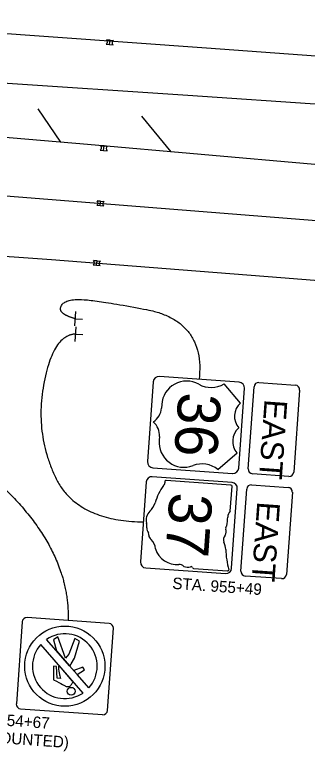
# Model space of a CAD drawing. Extents: x 1847379 to 1850904, y 217032 to 220169.
# Drawn here: x 1849667.4 to 1849731.4, y 218655.8 to 218816.8 of the extents above; entities that cross this region are included whole.
import ezdxf

# ---------------------------------------------------------------- set-up
doc = ezdxf.new("R2010")
doc.units = 0
for name, color, linetype in [('PM_P_Cells', 7, 'Continuous'), ('PM_P_CL_Double_Solid', 7, 'Continuous'), ('PM_P_Edge_Line', 7, 'Continuous'), ('PM_P_Lane_Line', 7, 'Continuous'), ('PM_P_Transverse_Line', 7, 'Continuous'), ('SN_X_Public', 7, 'Continuous'), ('SN_X_Text', 7, 'Continuous')]:
    doc.layers.add(name, color=color, linetype=linetype)

msp = doc.modelspace()

# ---------------------------------------------------------------- linework, layer by layer
at = {"layer": 'PM_P_Cells'}
for p, q in [((1849687.36, 218810.41), (1849688.13, 218810.34)), ((1849687.36, 218810.41), (1849688.13, 218810.34)), ((1849688.22, 218811.31), (1849687.45, 218811.38)), ((1849687.45, 218811.38), (1849688.22, 218811.31)), ((1849688.13, 218810.34), (1849688.22, 218811.31)), ((1849688.13, 218810.34), (1849688.9, 218810.27)), ((1849688.22, 218811.31), (1849688.98, 218811.24)), ((1849686.91, 218788.14), (1849686.14, 218788.21)), ((1849686.14, 218788.21), (1849686.91, 218788.14)), ((1849686.82, 218787.17), (1849686.91, 218788.14)), ((1849686.91, 218788.14), (1849687.68, 218788.07)), ((1849686.05, 218787.24), (1849686.82, 218787.17)), ((1849686.05, 218787.24), (1849686.82, 218787.17)), ((1849686.82, 218787.17), (1849687.59, 218787.1)), ((1849685.31, 218775.18), (1849686.08, 218775.11)), ((1849685.31, 218775.18), (1849686.08, 218775.11)), ((1849686.17, 218776.08), (1849685.4, 218776.15)), ((1849685.4, 218776.15), (1849686.17, 218776.08)), ((1849686.08, 218775.11), (1849686.17, 218776.08)), ((1849686.08, 218775.11), (1849686.85, 218775.04)), ((1849686.17, 218776.08), (1849686.94, 218776.01)), ((1849684.51, 218762.14), (1849685.28, 218762.07)), ((1849684.51, 218762.14), (1849685.28, 218762.07)), ((1849685.37, 218763.05), (1849684.6, 218763.12)), ((1849684.6, 218763.12), (1849685.37, 218763.05)), ((1849685.28, 218762.07), (1849685.37, 218763.05)), ((1849685.28, 218762.07), (1849686.05, 218762.01)), ((1849685.37, 218763.05), (1849686.14, 218762.98))]:
    msp.add_line(p, q, dxfattribs=at)
for centre, start, end in [((1849687.1, 218810.92), 296.8063, 52.8586), ((1849687.1, 218810.92), 296.8063, 52.8586), ((1849689.24, 218810.73), 116.8063, 232.8586), ((1849685.79, 218787.75), 296.8063, 52.8586), ((1849685.79, 218787.75), 296.8063, 52.8586), ((1849687.94, 218787.56), 116.8063, 232.8586), ((1849685.05, 218775.69), 296.8063, 52.8586), ((1849685.05, 218775.69), 296.8063, 52.8586), ((1849687.2, 218775.5), 116.8063, 232.8586), ((1849684.25, 218762.66), 296.8063, 52.8586), ((1849684.25, 218762.66), 296.8063, 52.8586), ((1849686.4, 218762.46), 116.8063, 232.8586)]:
    msp.add_arc(centre, 0.576, start, end, dxfattribs=at)
at = {"layer": 'PM_P_CL_Double_Solid'}
for p, q in [((1849693.11, 218799.32), (1849693.11, 218799.32)), ((1849683.32, 218788.47), (1849634.02, 218792.58)), ((1849733.07, 218784.06), (1849683.32, 218788.47))]:
    msp.add_line(p, q, dxfattribs=at)
at = {"layer": 'PM_P_Edge_Line'}
for p, q in [((1849655.22, 218802.6), (1849705.27, 218799.28)), ((1849705.27, 218799.28), (1849757.46, 218795.73))]:
    msp.add_line(p, q, dxfattribs=at)
msp.add_lwpolyline([(1849624.07, 218766.93), (1849675.44, 218763.35), (1849725.59, 218759.36), (1849777.06, 218755.28), (1849832.17, 218750.77)], dxfattribs=at)
at = {"layer": 'PM_P_Lane_Line'}
msp.add_line((1849606.07, 218781.96), (1849881.96, 218760.04), dxfattribs=at)
msp.add_lwpolyline([(1849608.14, 218816.84), (1849659.46, 218813.21), (1849709.31, 218809.62), (1849760.21, 218805.9), (1849807.22, 218802.44), (1849857.63, 218799.12), (1849906.82, 218795.7), (1849957.46, 218791.82), (1850014.55, 218787.19), (1850067.13, 218782.71), (1850118.03, 218778.2), (1850167.47, 218773.95), (1850186.14, 218772.34)], dxfattribs=at)
at = {"layer": 'PM_P_Transverse_Line'}
for p, q in [((1849672.4, 218796.24), (1849677.4, 218788.96)), ((1849695.12, 218794.63), (1849701.53, 218786.86))]:
    msp.add_line(p, q, dxfattribs=at)
at = {"layer": 'SN_X_Public'}
for p, q in [((1849680.52, 218748.78), (1849680.76, 218751.97)), ((1849680.64, 218750.37), (1849682.23, 218750.25)), ((1849680.57, 218745.42), (1849680.81, 218748.61)), ((1849680.69, 218747.02), (1849682.29, 218746.89)), ((1849716.78, 218731.93), (1849713.17, 218736.11)), ((1849720.81, 218736.42), (1849728.79, 218735.85)), ((1849718.46, 218717.54), (1849719.74, 218735.49)), ((1849729.72, 218734.78), (1849728.44, 218716.83)), ((1849699.53, 218731.6), (1849699.47, 218730.82)), ((1849699.03, 218724.58), (1849698.97, 218723.81)), ((1849711.83, 218717.41), (1849716.01, 218721.02)), ((1849727.37, 218715.9), (1849719.39, 218716.47)), ((1849714.69, 218713.98), (1849700.49, 218715)), ((1849714.53, 218708.3), (1849714.92, 218713.78)), ((1849719.21, 218714.05), (1849727.19, 218713.48)), ((1849716.87, 218695.17), (1849718.15, 218713.12)), ((1849728.12, 218712.41), (1849726.84, 218694.46)), ((1849706.52, 218695.77), (1849713.95, 218695.24)), ((1849706.52, 218695.77), (1849706.52, 218695.77)), ((1849725.77, 218693.53), (1849717.79, 218694.1)), ((1849676.81, 218680.78), (1849675.88, 218680.17)), ((1849676.81, 218680.78), (1849675.88, 218680.17)), ((1849675.88, 218680.17), (1849676.51, 218677.77)), ((1849675.88, 218680.17), (1849676.51, 218677.77)), ((1849678.45, 218676.14), (1849676.81, 218680.78)), ((1849678.45, 218676.14), (1849676.81, 218680.78)), ((1849680.53, 218680.43), (1849679.23, 218676.99)), ((1849680.53, 218680.43), (1849679.23, 218676.99)), ((1849680.42, 218676.14), (1849681.52, 218679.85)), ((1849680.42, 218676.14), (1849681.52, 218679.85)), ((1849681.52, 218679.85), (1849680.53, 218680.43)), ((1849681.52, 218679.85), (1849680.53, 218680.43)), ((1849682.31, 218668.52), (1849673.09, 218679.16)), ((1849676.51, 218677.77), (1849679.37, 218674.47)), ((1849679.23, 218676.99), (1849678.45, 218676.14)), ((1849679.23, 218676.99), (1849678.45, 218676.14)), ((1849679.42, 218674.41), (1849679.73, 218674.9)), ((1849679.42, 218674.41), (1849679.73, 218674.9)), ((1849679.73, 218674.9), (1849680.42, 218676.14)), ((1849679.73, 218674.9), (1849680.42, 218676.14)), ((1849676.47, 218674.33), (1849675.83, 218674.43)), ((1849675.83, 218674.43), (1849675.85, 218671.43)), ((1849676.47, 218674.33), (1849675.83, 218674.43)), ((1849675.83, 218674.43), (1849675.85, 218671.43)), ((1849676.65, 218671.78), (1849676.47, 218674.33)), ((1849676.65, 218671.78), (1849676.47, 218674.33)), ((1849680.04, 218671.13), (1849677.06, 218674.57)), ((1849679.37, 218674.47), (1849679.42, 218674.41)), ((1849682.3, 218674.2), (1849680.28, 218673.43)), ((1849682.3, 218674.2), (1849680.28, 218673.43)), ((1849680.28, 218673.43), (1849680.43, 218673.25)), ((1849681.04, 218672.55), (1849682.66, 218673.59)), ((1849681.04, 218672.55), (1849682.66, 218673.59)), ((1849682.66, 218673.59), (1849682.3, 218674.2)), ((1849682.66, 218673.59), (1849682.3, 218674.2)), ((1849677.38, 218671.7), (1849676.65, 218671.78)), ((1849677.38, 218671.7), (1849676.65, 218671.78)), ((1849675.85, 218671.43), (1849675.87, 218671.43)), ((1849675.85, 218671.43), (1849675.87, 218671.43)), ((1849680.14, 218671.02), (1849680.04, 218671.13))]:
    msp.add_line(p, q, dxfattribs=at)
for points in [[(1849716.48, 218736.5), (1849699.03, 218737.74)], [(1849697.69, 218736.58), (1849696.45, 218719.13)], [(1849716.4, 218717.71), (1849717.64, 218735.16)], [(1849697.6, 218717.79), (1849715.06, 218716.55)], [(1849714.92, 218714.58), (1849697.46, 218715.82)], [(1849696.13, 218714.67), (1849694.88, 218697.21)], [(1849714.83, 218695.79), (1849716.08, 218713.24)], [(1849696.04, 218695.87), (1849713.5, 218694.63)], [(1849688.02, 218683.74), (1849670.07, 218685.02)], [(1849669, 218684.09), (1849667.72, 218666.14)], [(1849687.67, 218664.71), (1849688.95, 218682.67)], [(1849680.43, 218673.25), (1849679.37, 218674.47), (1849675.93, 218678.43), (1849674.35, 218680.26)], [(1849683.58, 218669.62), (1849681.07, 218672.51), (1849680.42, 218673.25), (1849680.43, 218673.25)], [(1849680.43, 218673.25), (1849681.04, 218672.55), (1849681.04, 218672.55)], [(1849680.04, 218671.13), (1849680.04, 218671.13)], [(1849668.64, 218665.07), (1849686.6, 218663.79)]]:
    msp.add_lwpolyline(points, dxfattribs=at)
for centre, radius in [((1849678.33, 218674.39), 8.77), ((1849679.72, 218668.9), 0.864)]:
    msp.add_circle(centre, radius, dxfattribs=at)
for centre, radius, start, end in [((1849698.94, 218736.5), 1.25, 85.9213, 175.9213), ((1849704.99, 218731.27), 5.47, 60.7533, 176.5596), ((1849710.36, 218740.8), 5.47, 240.4685, 300.9223), ((1849716.39, 218735.25), 1.25, 355.9213, 85.9213), ((1849720.74, 218735.42), 1, 85.9213, 175.9213), ((1849728.72, 218734.85), 1, 355.9213, 85.9213), ((1849719.37, 218729.01), 3.91, 131.4943, 220.3483), ((1849695.58, 218731.1), 3.91, 302.7912, 355.9213), ((1849695.13, 218724.86), 3.91, 355.9213, 49.0514), ((1849718.98, 218723.55), 3.91, 131.4943, 220.3483), ((1849704.42, 218723.36), 5.47, 175.2831, 291.0894), ((1849697.69, 218719.04), 1.25, 175.9213, 265.9213), ((1849708.38, 218713.16), 5.47, 50.9204, 111.3742), ((1849715.15, 218717.8), 1.25, 265.9213, 355.9213), ((1849719.46, 218717.47), 1, 175.9213, 265.9213), ((1849727.44, 218716.9), 1, 265.9213, 355.9213), ((1849697.38, 218714.58), 1.25, 85.9213, 175.9213), ((1849711.84, 218705.96), 14.36, 146.3343, 163.1198), ((1849699.63, 218714.46), 0.603, 295.6697, 359.1931), ((1849701.89, 218714.64), 1.67, 173.2603, 186.5252), ((1849700.44, 218714.78), 0.219, 77.8797, 164.228), ((1849714.7, 218713.77), 0.217, 4.0514, 94.0514), ((1849714.83, 218713.33), 1.25, 355.9213, 85.9213), ((1849719.14, 218713.05), 1, 85.9213, 175.9213), ((1849727.12, 218712.48), 1, 355.9213, 85.9213), ((1849693.83, 218711.54), 4.49, 313.1055, 341.7573), ((1849698.98, 218706.3), 2.85, 136.6217, 192.2132), ((1849716.08, 218706.88), 2.11, 137.5409, 177.0332), ((1849693.95, 218705), 2.34, 351.6165, 17.1313), ((1849706.41, 218706.87), 7.56, 346.408, 0.9096), ((1849697.78, 218704.52), 1.52, 174.6984, 221.4706), ((1849712.42, 218703.83), 1.26, 320.388, 25.0625), ((1849714.12, 218704.6), 0.608, 125.7134, 203.0237), ((1849696.31, 218703.25), 0.428, 331.6731, 38.5698), ((1849698.27, 218703.29), 1.61, 188.7945, 229.1985), ((1849714.55, 218702.04), 1.52, 139.7776, 200.7495), ((1849695.42, 218700.04), 2.72, 0.3245, 48.4981), ((1849709.56, 218699.7), 4, 3.2675, 26.6902), ((1849702.87, 218701.61), 4.97, 198.2302, 274.9072), ((1849733.42, 218700.55), 19.88, 181.7658, 194.8278), ((1849696.13, 218697.12), 1.25, 175.9213, 265.9213), ((1849703.36, 218695.24), 1.41, 42.7278, 92.8509), ((1849705.19, 218697.97), 1.94, 245.9543, 289.5709), ((1849705.98, 218695.85), 0.323, 13.8653, 116.2583), ((1849706.51, 218695.99), 0.223, 195.5252, 273.6555), ((1849713.59, 218695.88), 1.25, 265.9213, 355.9213), ((1849713.99, 218695.44), 0.209, 257.7834, 3.6593), ((1849717.86, 218695.1), 1, 175.9213, 265.9213), ((1849725.84, 218694.53), 1, 265.9213, 355.9213), ((1849669.99, 218684.02), 1, 85.9213, 175.9213), ((1849687.95, 218682.74), 1, 355.9213, 85.9213), ((1849678.33, 218674.39), 7.09, 317.7693, 124.1693), ((1849678.33, 218674.39), 7.09, 317.7693, 124.1693), ((1849678.33, 218674.39), 7.09, 137.7404, 304.0927), ((1849668.71, 218666.06), 1, 175.9213, 265.9213), ((1849686.67, 218664.78), 1, 265.9213, 355.9213)]:
    msp.add_arc(centre, radius, start, end, dxfattribs=at)
for points in [[(1849677.06, 218674.57), (1849677.02, 218674.51), (1849676.94, 218674.31), (1849676.94, 218673.85), (1849677, 218673.43), (1849677.14, 218672.69), (1849677.26, 218672.18), (1849677.38, 218671.7)], [(1849677.06, 218674.57), (1849677.02, 218674.51), (1849676.94, 218674.31), (1849676.94, 218673.85), (1849677, 218673.43), (1849677.14, 218672.69), (1849677.26, 218672.18), (1849677.38, 218671.7)], [(1849675.87, 218671.43), (1849676.72, 218670.98), (1849678.06, 218670.25), (1849678.55, 218669.98), (1849678.72, 218669.94), (1849678.88, 218669.92), (1849679.28, 218669.9), (1849679.82, 218670.33), (1849680.01, 218670.76), (1849680.14, 218671.02)], [(1849675.87, 218671.43), (1849676.72, 218670.98), (1849678.06, 218670.25), (1849678.55, 218669.98), (1849678.72, 218669.94), (1849678.88, 218669.92), (1849679.28, 218669.9), (1849679.82, 218670.33), (1849680.01, 218670.76), (1849680.14, 218671.02)]]:
    msp.add_open_spline(points, degree=3, dxfattribs=at)
at = {"layer": 'SN_X_Text'}
for points in [[(1849680.64, 218750.37), (1849677.04, 218751.33), (1849677.78, 218754.34), (1849683.48, 218754.8), (1849708.98, 218749.93), (1849707.75, 218737.12)], [(1849680.69, 218747.02), (1849675.76, 218746.88), (1849671.7, 218725.5), (1849680.71, 218706.16), (1849695.51, 218705.94)], [(1849596.59, 218740), (1849622.52, 218734.68), (1849656.27, 218723.03), (1849679.46, 218697.82), (1849679.04, 218684.38)]]:
    msp.add_open_spline(points, degree=2, dxfattribs=at)

# ---------------------------------------------------------------- texts
at = {"layer": 'SN_X_Public'}
for s, height, p in [('36', 9.375, (1849703.25, 218734.42)), ('EAST', 5, (1849722.06, 218732.84)), ('37', 9.375, (1849701.32, 218712.53)), ('EAST', 5, (1849720.46, 218710.47))]:
    msp.add_text(s, height=height, rotation=265.9213, dxfattribs=at).set_placement(p)
at = {"layer": 'SN_X_Text'}
for s, p in [('STA. 955+49', (1849701.79, 218691.32)), ('STA. 954+67', (1849655.36, 218662.08)), ('(POLE MOUNTED)', (1849650.23, 218658.54))]:
    msp.add_text(s, height=2.5, rotation=355.9213, dxfattribs=at).set_placement(p)

doc.saveas('drawing.dxf')
